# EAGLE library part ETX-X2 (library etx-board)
ISA Bus ETX Board Connector 100 Pos. Source: www.kontron.com/techlib/whitepapers/etx_spec.pdf
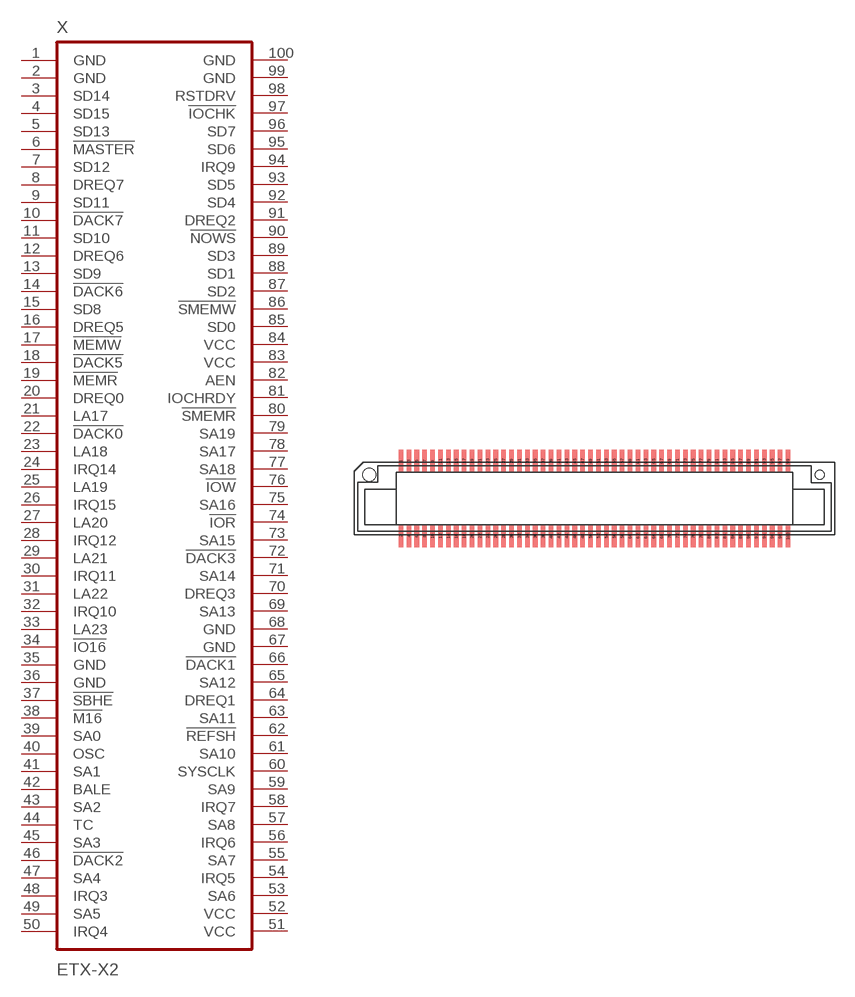
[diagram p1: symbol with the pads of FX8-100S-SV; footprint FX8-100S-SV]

Designator prefix X

## ETX-X2  [FX8-100S-SV]
1  GND  pwr
2  GND  pwr
3  SD14
4  SD15
5  SD13
6  !MASTER
7  SD12
8  DREQ7
9  SD11
10  !DACK7
11  SD10
12  DREQ6
13  SD9
14  !DACK6
15  SD8
16  DREQ5
17  !MEMW
18  !DACK5
19  !MEMR
20  DREQ0
21  LA17
22  !DACK0
23  LA18
24  IRQ14
25  LA19
26  IRQ15
27  LA20
28  IRQ12
29  LA21
30  IRQ11
31  LA22
32  IRQ10
33  LA23
34  !IO16
35  GND  pwr
36  GND  pwr
37  !SBHE
38  !M16
39  SA0
40  OSC
41  SA1
42  BALE
43  SA2
44  TC
45  SA3
46  !DACK2
47  SA4
48  IRQ3
49  SA5
50  IRQ4
51  VCC  pwr
52  VCC  pwr
53  SA6
54  IRQ5
55  SA7
56  IRQ6
57  SA8
58  IRQ7
59  SA9
60  SYSCLK
61  SA10
62  !REFSH
63  SA11
64  DREQ1
65  SA12
66  !DACK1
67  GND  pwr
68  GND  pwr
69  SA13
70  DREQ3
71  SA14
72  !DACK3
73  SA15
74  !IOR
75  SA16
76  !IOW
77  SA18
78  SA17
79  SA19
80  !SMEMR
81  IOCHRDY
82  AEN
83  VCC  pwr
84  VCC  pwr
85  SD0
86  !SMEMW
87  SD2
88  SD1
89  SD3
90  !NOWS
91  DREQ2
92  SD4
93  SD5
94  IRQ9
95  SD6
96  SD7
97  !IOCHK
98  RSTDRV
99  GND  pwr
100  GND  pwr

## Footprint FX8-100S-SV (pad centres in mm)
HIROSE - ETX Board Connector 100 Pos. Source: www.hirose.co.jp/cataloge_hp/e57800016.pdf www.kontron.com/techlib/whitepapers/etx_spec.pdf
smd 0.35 x 1.7: 1 -14.7,2.85; 2 -14.7,-2.85; 3 -14.1,2.85; 4 -14.1,-2.85; 5 -13.5,2.85; 6 -13.5,-2.85; 7 -12.9,2.85; 8 -12.9,-2.85; 9 -12.3,2.85; 10 -12.3,-2.85; 11 -11.7,2.85; 12 -11.7,-2.85; 13 -11.1,2.85; 14 -11.1,-2.85; 15 -10.5,2.85; 16 -10.5,-2.85; 17 -9.9,2.85; 18 -9.9,-2.85; 19 -9.3,2.85; 20 -9.3,-2.85; 21 -8.7,2.85; 22 -8.7,-2.85; 23 -8.1,2.85; 24 -8.1,-2.85; 25 -7.5,2.85; 26 -7.5,-2.85; 27 -6.9,2.85; 28 -6.9,-2.85; 29 -6.3,2.85; 30 -6.3,-2.85; 31 -5.7,2.85; 32 -5.7,-2.85; 33 -5.1,2.85; 34 -5.1,-2.85; 35 -4.5,2.85; 36 -4.5,-2.85; 37 -3.9,2.85; 38 -3.9,-2.85; 39 -3.3,2.85; 40 -3.3,-2.85; 41 -2.7,2.85; 42 -2.7,-2.85; 43 -2.1,2.85; 44 -2.1,-2.85; 45 -1.5,2.85; 46 -1.5,-2.85; 47 -0.9,2.85; 48 -0.9,-2.85; 49 -0.3,2.85; 50 -0.3,-2.85; 51 0.3,2.85; 52 0.3,-2.85; 53 0.9,2.85; 54 0.9,-2.85; 55 1.5,2.85; 56 1.5,-2.85; 57 2.1,2.85; 58 2.1,-2.85; 59 2.7,2.85; 60 2.7,-2.85; 61 3.3,2.85; 62 3.3,-2.85; 63 3.9,2.85; 64 3.9,-2.85; 65 4.5,2.85; 66 4.5,-2.85; 67 5.1,2.85; 68 5.1,-2.85; 69 5.7,2.85; 70 5.7,-2.85; 71 6.3,2.85; 72 6.3,-2.85; 73 6.9,2.85; 74 6.9,-2.85; 75 7.5,2.85; 76 7.5,-2.85; 77 8.1,2.85; 78 8.1,-2.85; 79 8.7,2.85; 80 8.7,-2.85; 81 9.3,2.85; 82 9.3,-2.85; 83 9.9,2.85; 84 9.9,-2.85; 85 10.5,2.85; 86 10.5,-2.85; 87 11.1,2.85; 88 11.1,-2.85; 89 11.7,2.85; 90 11.7,-2.85; 91 12.3,2.85; 92 12.3,-2.85; 93 12.9,2.85; 94 12.9,-2.85; 95 13.5,2.85; 96 13.5,-2.85; 97 14.1,2.85; 98 14.1,-2.85; 99 14.7,2.85; 100 14.7,-2.85
hole 1 at -17.1,1.8
hole 0.7 at 17.1,1.8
